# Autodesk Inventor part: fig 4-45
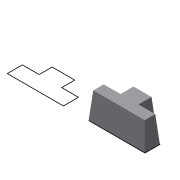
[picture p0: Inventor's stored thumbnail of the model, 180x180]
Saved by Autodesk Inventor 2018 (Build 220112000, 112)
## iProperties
Created: 2004-05
Part Number: fig 4-45
Document SubType Name: Modeling
Designer: CADCIM Technologies
Manufacturer: Standard
Standards Organization: Custom
Density: 1 g/cm^3
Material: Generic
Appearance: Default
Author: CADCIM Technologies
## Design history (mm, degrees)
sketch "Sketch1"
  geometry: L1 (31.783, 34.561)-(31.783, 22.933); L2 (31.783, 22.933)-(16.796, 22.933); L3 (16.796, 22.933)-(16.796, 9.496); L4 (16.796, 9.496)-(66.925, 9.496); L5 (66.925, 9.496)-(66.925, 22.933); L6 (66.925, 22.933)-(51.938, 22.933); L7 (51.938, 22.933)-(51.938, 34.561); L8 (51.938, 34.561)-(31.783, 34.561); L9 (-41.013, 34.561)-(-41.013, 22.933); L10 (-41.013, 22.933)-(-56, 22.933); L11 (-56, 22.933)-(-56, 9.496); L12 (-56, 9.496)-(-5.871, 9.496); L13 (-5.871, 9.496)-(-5.871, 22.933); L14 (-5.871, 22.933)-(-20.858, 22.933); L15 (-20.858, 22.933)-(-20.858, 34.561); L16 (-20.858, 34.561)-(-41.013, 34.561)
  constraints: 32 end point, 10 parallel, 4 equal length, 2 collinear, 2 perpendicular, 2 vertical
extrude "Extrusion1" new body sketch "Sketch1" distance "d0" = 23.25; taper "d1" = -5 deg
body "Solid1"
